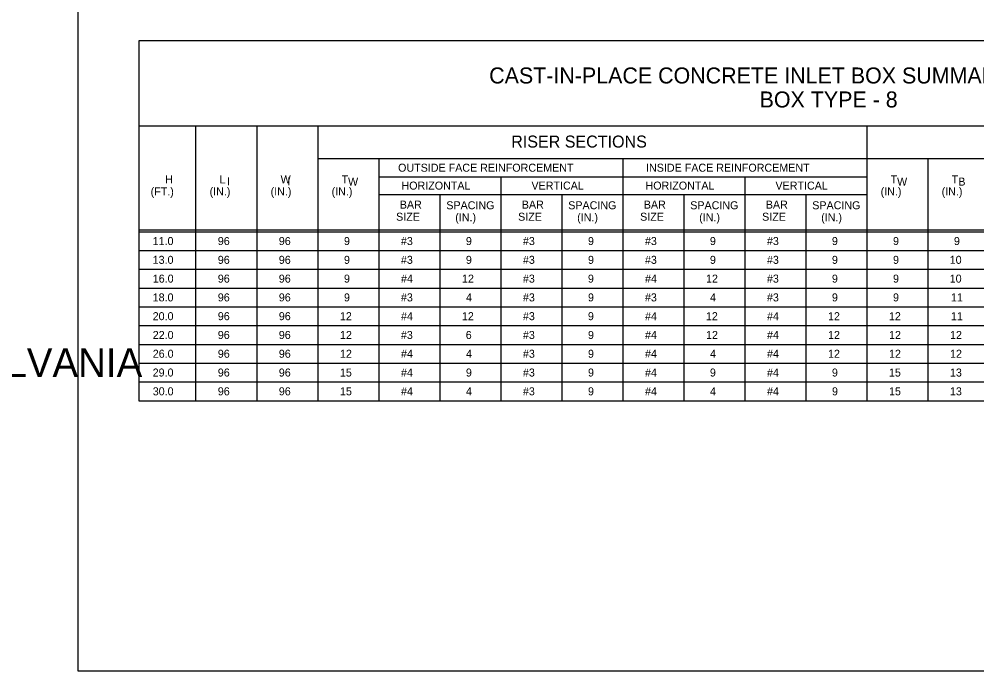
# Model space of a CAD drawing. Extents: x -6420 to 49575, y -4552 to 11624.
# Drawn here: x -3605 to -2428, y 3878 to 4679 of the extents above; entities that cross this region are included whole.
import ezdxf

# ---------------------------------------------------------------- set-up
doc = ezdxf.new("R2010")
doc.units = 0
doc.layers.add('1', color=7, linetype='Continuous')

msp = doc.modelspace()

# ---------------------------------------------------------------- linework, layer by layer
at = {"layer": '1'}
for p, q in [((-3458.2, 4652.6), (-3458.2, 4210.1)), ((-1663.2, 4652.6), (-3458.2, 4652.6)), ((-1663.2, 4547.6), (-3458.2, 4547.6)), ((-3388.2, 4210.1), (-3388.2, 4547.6)), ((-3313.2, 4547.6), (-3313.2, 4210.1)), ((-3238.2, 4547.6), (-3238.2, 4210.1)), ((-2563.2, 4547.6), (-2563.2, 4210.1)), ((-1663.2, 4507.6), (-3238.2, 4507.6)), ((-3163.2, 4507.6), (-3163.2, 4210.1)), ((-2863.2, 4507.6), (-2863.2, 4210.1)), ((-2488.2, 4507.6), (-2488.2, 4210.1)), ((-3163.2, 4485.6), (-2863.2, 4485.6)), ((-3013.2, 4485.6), (-3013.2, 4210.1)), ((-2863.2, 4485.6), (-2563.2, 4485.6)), ((-2713.2, 4485.6), (-2713.2, 4210.1)), ((-3163.2, 4463.6), (-2863.2, 4463.6)), ((-3088.2, 4463.6), (-3088.2, 4210.1)), ((-2938.2, 4463.6), (-2938.2, 4210.1)), ((-2863.2, 4463.6), (-2563.2, 4463.6)), ((-2788.2, 4463.6), (-2788.2, 4210.1)), ((-2638.2, 4463.6), (-2638.2, 4210.1)), ((-3458.2, 4420.4), (-1663.2, 4420.4)), ((-3458.2, 4417.9), (-1663.2, 4417.9)), ((-3458.2, 4394.8), (-1663.2, 4394.8)), ((-3458.2, 4371.7), (-1663.2, 4371.7)), ((-3458.2, 4348.6), (-1663.2, 4348.6)), ((-3458.2, 4325.5), (-1663.2, 4325.5)), ((-3458.2, 4302.4), (-1663.2, 4302.4)), ((-3458.2, 4279.3), (-1663.2, 4279.3)), ((-3458.2, 4256.3), (-1663.2, 4256.3)), ((-3458.2, 4233.2), (-1663.2, 4233.2)), ((-3458.2, 4210.1), (-1663.2, 4210.1))]:
    msp.add_line(p, q, dxfattribs=at)
msp.add_lwpolyline([(-954.5, 3877.8), (-954.5, 5728.2), (-3533.2, 5728.2), (-3533.2, 3877.8), (-954.5, 3877.8), (-954.5, 3964.3), (-1610.7, 3964.3), (-1610.7, 4176.5), (-954.5, 4176.5), (-954.5, 4271.5), (-1610.7, 4271.5), (-1610.7, 3877.8), (-1352.1, 3877.8), (-1352.1, 3964.3), (-1352.1, 3877.8), (-1099.5, 3877.8), (-1099.5, 3964.3), (-1099.5, 3923.9), (-954.5, 3923.9)], dxfattribs=at)

# ---------------------------------------------------------------- texts
for s, height, p in [('CAST-IN-PLACE CONCRETE INLET BOX SUMMARY TABLE', 19.685, (-3027.5, 4600.2)), ('BOX TYPE - 8', 19.685, (-2695, 4570.7)), ('RISER SECTIONS', 14.764, (-3000.4, 4521.4)), ('OUTSIDE FACE REINFORCEMENT', 9.843, (-3139.5, 4491.7)), ('INSIDE FACE REINFORCEMENT', 9.843, (-2834.6, 4491.7)), ('H', 9.84, (-3426, 4477.3)), ('L ', 9.84, (-3358.9, 4477.3)), ('W ', 9.84, (-3283.9, 4477.3)), ('T ', 9.84, (-3208.9, 4477.3)), ('T ', 9.84, (-2533.9, 4477.3)), ('T ', 9.84, (-2458.9, 4477.3)), ('I', 9.84, (-3349.9, 4474.8)), ('I', 9.84, (-3275.5, 4474.8)), ('W', 9.84, (-3201, 4474.6)), ('HORIZONTAL', 9.84, (-3135.3, 4469.7)), ('VERTICAL', 9.84, (-2975.5, 4469.7)), ('HORIZONTAL', 9.84, (-2835.3, 4469.7)), ('VERTICAL', 9.84, (-2675.5, 4469.7)), ('W', 9.84, (-2526, 4474.6)), ('B', 9.84, (-2450.7, 4474.6)), ('(FT.)', 9.84, (-3443.7, 4462.5)), ('(IN.)', 9.84, (-3371.2, 4462.5)), ('(IN.)', 9.84, (-3296.2, 4462.5)), ('(IN.)', 9.84, (-3221.2, 4462.5)), ('(IN.)', 9.84, (-2546.2, 4462.5)), ('(IN.)', 9.84, (-2471.2, 4462.5)), ('BAR', 9.84, (-3137.4, 4446.3)), ('SPACING', 9.84, (-3080.2, 4445.5)), ('BAR', 9.84, (-2987.4, 4446.3)), ('SPACING', 9.84, (-2930.3, 4445.5)), ('BAR', 9.84, (-2837.4, 4446.3)), ('SPACING', 9.84, (-2780.3, 4445.5)), ('BAR', 9.84, (-2687.4, 4446.3)), ('SPACING', 9.84, (-2630.3, 4445.5)), ('SIZE', 9.84, (-3141.9, 4431.4)), ('(IN.)', 9.84, (-3069.2, 4430.7)), ('SIZE', 9.84, (-2991.9, 4431.4)), ('(IN.)', 9.84, (-2919.3, 4430.7)), ('SIZE', 9.84, (-2841.9, 4431.4)), ('(IN.)', 9.84, (-2769.3, 4430.7)), ('SIZE', 9.84, (-2691.9, 4431.4)), ('(IN.)', 9.84, (-2619.3, 4430.7)), ('11.0', 9.84, (-3441.2, 4401.5)), ('96', 9.84, (-3361.1, 4401.5)), ('96', 9.84, (-3286.1, 4401.5)), ('9', 9.84, (-3206, 4401.5)), ('#3', 9.84, (-3136, 4401.5)), ('9', 9.84, (-3056.1, 4401.5)), ('#3', 9.84, (-2986, 4401.5)), ('9', 9.84, (-2906, 4401.5)), ('#3', 9.84, (-2836, 4401.5)), ('9', 9.84, (-2756.1, 4401.5)), ('#3', 9.84, (-2686, 4401.5)), ('9', 9.84, (-2606.1, 4401.5)), ('9', 9.84, (-2531, 4401.5)), ('9', 9.84, (-2456.1, 4401.5)), ('13.0', 9.84, (-3441.2, 4378.4)), ('96', 9.84, (-3361.1, 4378.4)), ('96', 9.84, (-3286.1, 4378.4)), ('9', 9.84, (-3206, 4378.4)), ('#3', 9.84, (-3136, 4378.4)), ('9', 9.84, (-3056.1, 4378.4)), ('#3', 9.84, (-2986, 4378.4)), ('9', 9.84, (-2906, 4378.4)), ('#3', 9.84, (-2836, 4378.4)), ('9', 9.84, (-2756.1, 4378.4)), ('#3', 9.84, (-2686, 4378.4)), ('9', 9.84, (-2606.1, 4378.4)), ('9', 9.84, (-2531, 4378.4)), ('10', 9.84, (-2461.3, 4378.4)), ('16.0', 9.84, (-3441.1, 4355.3)), ('96', 9.84, (-3361.1, 4355.3)), ('96', 9.84, (-3286.1, 4355.3)), ('9', 9.84, (-3206, 4355.3)), ('#4', 9.84, (-3135.9, 4355.3)), ('12', 9.84, (-3060.9, 4355.3)), ('#3', 9.84, (-2986, 4355.3)), ('9', 9.84, (-2906.1, 4355.3)), ('#4', 9.84, (-2835.9, 4355.3)), ('12', 9.84, (-2760.9, 4355.3)), ('#3', 9.84, (-2686, 4355.3)), ('9', 9.84, (-2606.1, 4355.3)), ('9', 9.84, (-2531, 4355.3)), ('10', 9.84, (-2461.3, 4355.3)), ('18.0', 9.84, (-3441.2, 4332.2)), ('96', 9.84, (-3361.1, 4332.2)), ('96', 9.84, (-3286.1, 4332.2)), ('9', 9.84, (-3206, 4332.2)), ('#3', 9.84, (-3136, 4332.2)), ('4', 9.84, (-3056, 4332.2)), ('#3', 9.84, (-2986, 4332.2)), ('9', 9.84, (-2906, 4332.2)), ('#3', 9.84, (-2836, 4332.2)), ('4', 9.84, (-2756, 4332.2)), ('#3', 9.84, (-2686, 4332.2)), ('9', 9.84, (-2606.1, 4332.2)), ('9', 9.84, (-2531, 4332.2)), ('11', 9.84, (-2459.8, 4332.2)), ('20.0', 9.84, (-3441.2, 4309.1)), ('96', 9.84, (-3361.1, 4309.1)), ('96', 9.84, (-3286.1, 4309.1)), ('12', 9.84, (-3211, 4309.1)), ('#4', 9.84, (-3135.9, 4309.1)), ('12', 9.84, (-3061, 4309.1)), ('#3', 9.84, (-2986, 4309.1)), ('9', 9.84, (-2906.1, 4309.1)), ('#4', 9.84, (-2835.9, 4309.1)), ('12', 9.84, (-2761, 4309.1)), ('#4', 9.84, (-2685.9, 4309.1)), ('12', 9.84, (-2610.9, 4309.1)), ('12', 9.84, (-2536, 4309.1)), ('11', 9.84, (-2459.8, 4309.1)), ('22.0', 9.84, (-3441.1, 4286)), ('96', 9.84, (-3361.1, 4286)), ('96', 9.84, (-3286.1, 4286)), ('12', 9.84, (-3210.9, 4286)), ('#3', 9.84, (-3136, 4286)), ('6', 9.84, (-3056.3, 4286)), ('#3', 9.84, (-2986, 4286)), ('9', 9.84, (-2906, 4286)), ('#4', 9.84, (-2835.9, 4286)), ('12', 9.84, (-2760.9, 4286)), ('#4', 9.84, (-2685.9, 4286)), ('12', 9.84, (-2610.9, 4286)), ('12', 9.84, (-2535.9, 4286)), ('12', 9.84, (-2460.9, 4286)), ('COMMONWEALTH OF PENNSYLVANIA', 35.379, (-4326.7, 4239.2)), ('26.0', 9.84, (-3441.1, 4262.9)), ('96', 9.84, (-3361.1, 4262.9)), ('96', 9.84, (-3286.1, 4262.9)), ('12', 9.84, (-3210.9, 4262.9)), ('#4', 9.84, (-3135.9, 4262.9)), ('4', 9.84, (-3056, 4262.9)), ('#3', 9.84, (-2986, 4262.9)), ('9', 9.84, (-2906, 4262.9)), ('#4', 9.84, (-2835.9, 4262.9)), ('4', 9.84, (-2756, 4262.9)), ('#4', 9.84, (-2685.9, 4262.9)), ('12', 9.84, (-2610.9, 4262.9)), ('12', 9.84, (-2535.9, 4262.9)), ('12', 9.84, (-2460.9, 4262.9)), ('29.0', 9.84, (-3441.2, 4239.8)), ('96', 9.84, (-3361.1, 4239.8)), ('96', 9.84, (-3286.1, 4239.8)), ('15', 9.84, (-3211, 4239.8)), ('#4', 9.84, (-3135.9, 4239.8)), ('9', 9.84, (-3056.1, 4239.8)), ('#3', 9.84, (-2986, 4239.8)), ('9', 9.84, (-2906, 4239.8)), ('#4', 9.84, (-2835.9, 4239.8)), ('9', 9.84, (-2756.1, 4239.8)), ('#4', 9.84, (-2685.9, 4239.8)), ('9', 9.84, (-2606.1, 4239.8)), ('15', 9.84, (-2536, 4239.8)), ('13', 9.84, (-2461, 4239.8)), ('30.0', 9.84, (-3441.1, 4216.7)), ('96', 9.84, (-3361.1, 4216.7)), ('96', 9.84, (-3286.1, 4216.7)), ('15', 9.84, (-3210.9, 4216.7)), ('#4', 9.84, (-3135.9, 4216.7)), ('4', 9.84, (-3056, 4216.7)), ('#3', 9.84, (-2986, 4216.7)), ('9', 9.84, (-2906, 4216.7)), ('#4', 9.84, (-2835.9, 4216.7)), ('4', 9.84, (-2756, 4216.7)), ('#4', 9.84, (-2685.9, 4216.7)), ('9', 9.84, (-2606, 4216.7)), ('15', 9.84, (-2535.9, 4216.7)), ('13', 9.84, (-2461, 4216.7))]:
    msp.add_text(s, height=height, dxfattribs=at).set_placement(p)

doc.saveas('drawing.dxf')
